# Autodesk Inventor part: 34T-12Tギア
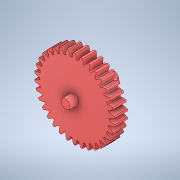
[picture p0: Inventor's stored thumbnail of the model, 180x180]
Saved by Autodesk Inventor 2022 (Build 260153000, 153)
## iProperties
CustomPartVersion: 1
Created: 2024-10
Part Number: 34T-12Tギア
Material: アセタール樹脂、白
Document SubType Name: Modeling
Designer: jsat7
Categories: <?xml version="1.0" encoding="UTF-16"?> <MemberInstance><Categories><FamilyTemplate><FamilyTemplateParameter ValueType="xs:double" Id="1" ObjectReferenceKey="da
Density: 1.425 g/cm^3
Appearance: 滑らか - 白
Author: jsat7
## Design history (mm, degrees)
sketch "Sketch1"
  geometry: C1 r 9 at (0, 0)
  constraints: 1 centre point
  dimensions: "d0" = 18 diameter of C1 (= da_da)
extrude "Extrusion1" new body sketch "Sketch1" distance "d1" = 3 (= da_b); taper "d2" = 0 deg
workplane "Work Plane2"
sketch "Sketch2"
  geometry: C1 r 9 at (0, 0) reference; C2 r 8.5 at (0, 0)
  constraints: 1 centre point, 1 coincident
  dimensions: "d3" = 17 diameter of C2 (= da_d)
feature "ピッチ円直径" sketch "Sketch2" dims "d4" = 10, "d5" = 0
workplane "Work Plane8"
workplane "Work Plane9"
feature "平歯車" dims "da_b" = 3, "da_d" = 17, "da_aw" = 5.75, "da_da" = 18, "da_df" = 15.75, "da_dw" = 17, angle "da_beta" = 0 deg, "da_lefttooth" = 0, "da_righttooth" = 0
sketch "スケッチ3"
  geometry: C1 r 1 at (0, 0); 1 further point
  constraints: 1 centre point, 1 coincident
  dimensions: "d49" = 2 diameter of C1
extrude "押し出し2" join sketch "スケッチ3" distance "d50" = 2; taper "d51" = 0 deg
sketch "スケッチ4"
  geometry: C1 r 1 at (0, 0); 1 further point
  constraints: 1 centre point, 1 coincident
  dimensions: "d52" = 2 diameter of C1
extrude "押し出し3" join sketch "スケッチ4" distance "d53" = 6; taper "d54" = 0 deg
sketch "スケッチ5"
  geometry: C1 r 3.5 at (0, 0); 1 further point
  constraints: 1 centre point
  dimensions: "d55" = 7 diameter of C1 (= d56)
extrude "押し出し4" join sketch "スケッチ5" distance "d57" = 4; taper "d58" = 0 deg
feature "iFeature1:1" dims "d59" = 570, "d60" = 120, "d61" = 10, "d62" = 0, "d63" = 0, "d64" = 6, "d65" = 4.75, "d66" = 7, "d67" = 6, "d68" = 0, "d69" = 4, "d70" = 11.25, "d71" = 120 (derived), "d72" = 360 deg, "d73" = 120 (derived), "d74" = 360 deg, "d75" = 120 (derived), "d76" = 360 deg, "d77" = 0, "d78" = 4 (derived)
body "Solid1"
body "Srf1"
other parameters: "d16" = 5.75 (= da_aw), "d17" = 0, "d34" = 0.924 (computed from da_z), "d39" = 0, "d41" = 0, "d43" = 5.75 (= da_aw), "d46" = 5.75 (= da_aw), "d47" = 0, "d48" = 0, "d56" = 7
